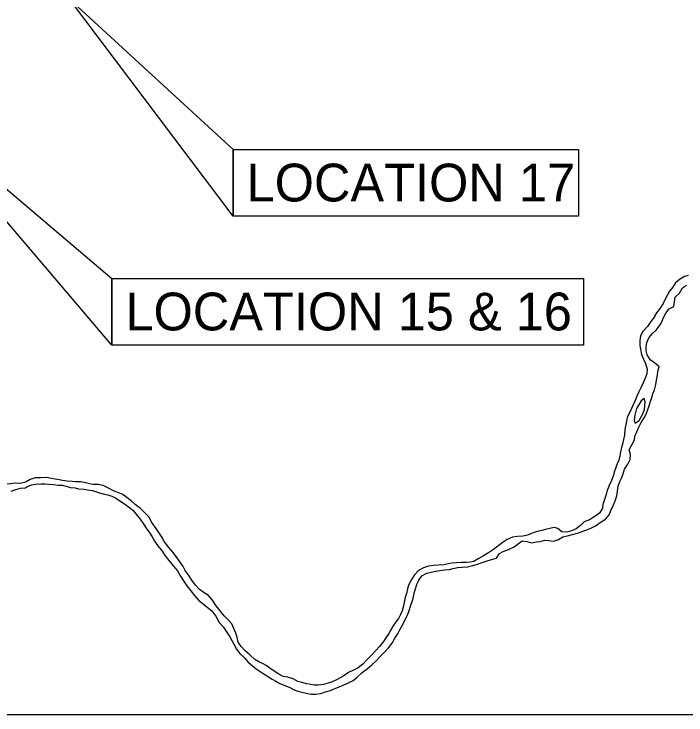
# Model space of a CAD drawing. Extents: x 0 to 34, y 0 to 22.
# Drawn here: x 10.628 to 13.652, y 13.067 to 16.221 of the extents above; entities that cross this region are included whole.
import ezdxf

# ---------------------------------------------------------------- set-up
doc = ezdxf.new("R2010")
doc.units = 0
for name, color, linetype in [('BR_P_Gen_Text', 7, 'Continuous'), ('GM_X_Major_River', 7, 'Continuous'), ('SH_Text', 7, 'Continuous')]:
    doc.layers.add(name, color=color, linetype=linetype)

msp = doc.modelspace()

# ---------------------------------------------------------------- linework, layer by layer
at = {"layer": 'BR_P_Gen_Text'}
for points in [[(11.6138, 15.6114), (11.6138, 15.3112), (10.8775, 16.2902)], [(11.0687, 15.0311), (11.0687, 14.7309), (10.1479, 15.8121)], [(11.6138, 15.6114), (13.1673, 15.6114), (13.1673, 15.3112), (11.6138, 15.3112)], [(11.0687, 15.0311), (13.1902, 15.0311), (13.1902, 14.7309), (11.0687, 14.7309)]]:
    msp.add_lwpolyline(points, close=True, dxfattribs=at)
at = {"layer": 'GM_X_Major_River'}
for points in [[(13.662, 15.0452), (13.6454, 15.0406), (13.6225, 15.0271), (13.604, 15.0116), (13.5907, 14.9911), (13.5773, 14.975), (13.5678, 14.9583), (13.5589, 14.9416), (13.5494, 14.9192), (13.5361, 14.8974), (13.5183, 14.8774), (13.5101, 14.8614), (13.5094, 14.8588)], [(13.5459, 14.8417), (13.5484, 14.8533), (13.5605, 14.8751), (13.5764, 14.895), (13.5968, 14.9053), (13.6005, 14.9258), (13.603, 14.9476), (13.6221, 14.9656), (13.636, 14.9887), (13.6539, 15.001)], [(13.5094, 14.8588), (13.4942, 14.8383), (13.4789, 14.8152), (13.4573, 14.7933), (13.4472, 14.7734), (13.4441, 14.7529), (13.4435, 14.7305), (13.4468, 14.7139), (13.452, 14.689), (13.4598, 14.6685), (13.4694, 14.6481), (13.4766, 14.6232), (13.476, 14.6021), (13.4678, 14.5822), (13.459, 14.561), (13.4482, 14.5392), (13.44, 14.5206), (13.4311, 14.502), (13.4235, 14.4828), (13.4134, 14.4623), (13.4064, 14.4462), (13.3975, 14.427), (13.3874, 14.4077), (13.3837, 14.3898), (13.3799, 14.3674), (13.3768, 14.3514), (13.3743, 14.3264), (13.3712, 14.3072), (13.3681, 14.2912), (13.3618, 14.2713), (13.3568, 14.2508), (13.3543, 14.2335), (13.3493, 14.2136), (13.3417, 14.197), (13.3366, 14.1803), (13.3303, 14.1636), (13.3234, 14.1419), (13.3158, 14.1226), (13.3063, 14.0995), (13.2975, 14.0771), (13.2905, 14.054), (13.2855, 14.0374), (13.2779, 14.0143), (13.2761, 13.9976), (13.2621, 13.9758), (13.2373, 13.9565), (13.2169, 13.9449), (13.1939, 13.9364), (13.1767, 13.9191), (13.1576, 13.9043), (13.1372, 13.8958), (13.1148, 13.89), (13.0931, 13.8905), (13.0751, 13.9058), (13.0585, 13.9102), (13.0387, 13.9056), (13.0195, 13.901), (13.0029, 13.8965), (12.9819, 13.8925), (12.9595, 13.8854), (12.9385, 13.8763), (12.918, 13.8717), (12.8938, 13.8697), (12.8708, 13.8677), (12.8465, 13.8573), (12.8242, 13.8418), (12.8045, 13.827), (12.7854, 13.8116), (12.7624, 13.7961), (12.7401, 13.7825), (12.7172, 13.7703), (12.6974, 13.758), (12.6808, 13.7541), (12.6635, 13.7527), (12.6412, 13.7526), (12.6188, 13.7512), (12.5984, 13.7505), (12.5817, 13.7478), (12.562, 13.7433), (12.5377, 13.7406), (12.5153, 13.7392), (12.4929, 13.7372), (12.4706, 13.7287), (12.4483, 13.7177), (12.4305, 13.6972), (12.4159, 13.676), (12.4032, 13.651), (12.3969, 13.6292), (12.3938, 13.6132)], [(12.6234, 13.7308), (12.6451, 13.7315), (12.6687, 13.7336), (12.6924, 13.7394), (12.7096, 13.744), (12.7307, 13.7511), (12.753, 13.7596), (12.7766, 13.7661), (12.799, 13.772), (12.8129, 13.7931), (12.8295, 13.8022), (12.8537, 13.8119), (12.878, 13.8235), (12.8984, 13.8384), (12.9149, 13.85), (12.936, 13.8481), (12.9572, 13.8412), (12.9789, 13.8458), (12.9961, 13.8484), (13.0166, 13.853), (13.0338, 13.8525), (13.0562, 13.8487), (13.0773, 13.8572), (13.0977, 13.8694), (13.1187, 13.8727), (13.1417, 13.8786), (13.1641, 13.8851), (13.1807, 13.8916), (13.2017, 13.8981), (13.224, 13.9084), (13.2438, 13.9188), (13.2693, 13.9355), (13.2891, 13.9478), (13.3062, 13.9684), (13.3157, 13.9902), (13.3259, 14.012), (13.3328, 14.0312), (13.341, 14.053), (13.3428, 14.0741), (13.3472, 14.0965), (13.3542, 14.117), (13.3611, 14.1331), (13.3694, 14.1523), (13.3757, 14.1728), (13.3896, 14.1953), (13.4004, 14.2171), (13.4016, 14.2389), (13.3964, 14.26), (13.4078, 14.2824), (13.4205, 14.3049), (13.421, 14.3215), (13.4305, 14.3414), (13.44, 14.3619), (13.4502, 14.3831), (13.4635, 14.4043), (13.473, 14.4203), (13.4799, 14.4415), (13.4856, 14.4575), (13.4913, 14.4793), (13.4982, 14.496), (13.502, 14.5126), (13.5102, 14.5299), (13.5165, 14.5543), (13.5196, 14.5741), (13.5234, 14.5965), (13.5246, 14.6138), (13.5309, 14.6343), (13.5078, 14.6528), (13.4917, 14.6636), (13.4769, 14.6878), (13.4724, 14.7064), (13.4723, 14.7224), (13.4761, 14.7435), (13.4843, 14.7646), (13.5008, 14.7839), (13.5174, 14.7987), (13.5352, 14.8225), (13.5459, 14.8417)], [(13.4631, 14.4913), (13.4497, 14.481), (13.4288, 14.4463), (13.4212, 14.4156), (13.4182, 14.3925), (13.4233, 14.3798)], [(13.4233, 14.3798), (13.4412, 14.3926), (13.4551, 14.4164), (13.4652, 14.4414), (13.4683, 14.4766), (13.4631, 14.4913)], [(12.3938, 13.6132), (12.3887, 13.5972), (12.3856, 13.5811), (12.38, 13.5587), (12.3743, 13.5357), (12.3667, 13.519), (12.3578, 13.5017), (12.3464, 13.4856), (12.3343, 13.4683), (12.3242, 13.4503), (12.3147, 13.4343), (12.3013, 13.4137), (12.2899, 13.397), (12.2727, 13.3752), (12.2568, 13.3566), (12.2365, 13.3366), (12.2174, 13.3173), (12.1977, 13.2961), (12.176, 13.2787), (12.1556, 13.2684), (12.1333, 13.258), (12.1122, 13.2439), (12.0957, 13.2335), (12.0784, 13.2258), (12.0599, 13.2167), (12.0421, 13.2102), (12.021, 13.2044), (11.9967, 13.2011), (11.9801, 13.201), (11.9622, 13.2035), (11.9462, 13.2079), (11.9225, 13.2129), (11.9046, 13.2179), (11.8835, 13.2299), (11.8598, 13.2375), (11.8393, 13.2406), (11.8195, 13.2507), (11.781, 13.2761), (11.765, 13.2876), (11.7464, 13.2984), (11.7304, 13.3066), (11.7124, 13.3174), (11.6893, 13.3378), (11.6675, 13.3562), (11.6495, 13.3753), (11.6373, 13.3944), (11.6321, 13.4175), (11.6269, 13.4353), (11.6179, 13.4558), (11.6076, 13.4775), (11.5902, 13.4972), (11.5742, 13.5138), (11.5555, 13.5355), (11.5382, 13.5578), (11.5214, 13.5839), (11.5028, 13.6049), (11.4797, 13.6195), (11.4631, 13.6323), (11.4451, 13.6514), (11.4284, 13.6737), (11.4142, 13.6947), (11.3988, 13.7171), (11.3885, 13.7349), (11.3756, 13.7553), (11.3582, 13.7796), (11.3428, 13.7993), (11.3248, 13.8203), (11.3055, 13.8465), (11.2952, 13.8656), (11.2804, 13.888), (11.2676, 13.9058), (11.2483, 13.9332), (11.2341, 13.9588), (11.2155, 13.9779), (11.1956, 13.997), (11.1731, 14.0141), (11.1545, 14.0307), (11.1302, 14.0498), (11.1141, 14.0612), (11.0981, 14.0662), (11.0764, 14.0757), (11.0527, 14.0884), (11.029, 14.0992), (11.0066, 14.1035), (10.9848, 14.1041), (10.9682, 14.1078), (10.9503, 14.1122), (10.9285, 14.116), (10.9055, 14.1158), (10.8895, 14.117), (10.8672, 14.1195), (10.8467, 14.1226), (10.8307, 14.1257), (10.8128, 14.1282), (10.7968, 14.1319), (10.7744, 14.135), (10.7469, 14.1349), (10.7239, 14.1335), (10.7003, 14.127), (10.6821, 14.1165), (10.6751, 14.1134)], [(10.6751, 14.1134), (10.6541, 14.1081), (10.633, 14.1099), (10.6113, 14.1078), (10.5889, 14.105)], [(10.6804, 14.0897), (10.6855, 14.0937), (10.7074, 14.1033), (10.7247, 14.1053), (10.749, 14.1067), (10.7662, 14.1075), (10.7841, 14.1056), (10.8065, 14.1038), (10.8276, 14.1014), (10.8442, 14.1008), (10.8666, 14.0958), (10.8826, 14.0908), (10.9035, 14.0887), (10.9184, 14.0852)], [(10.6147, 14.0745), (10.6364, 14.0817), (10.658, 14.087), (10.6804, 14.0897)], [(10.9184, 14.0852), (10.9427, 14.0834), (10.9587, 14.0809), (10.9805, 14.0772), (11.0125, 14.0671), (11.0285, 14.0627), (11.0509, 14.0577), (11.0675, 14.052), (11.0842, 14.0438), (11.1047, 14.0304), (11.1252, 14.0177), (11.1412, 14.0057), (11.1643, 13.9872), (11.1829, 13.9649), (11.1952, 13.9483), (11.2119, 13.9247), (11.2228, 13.9082), (11.2389, 13.8858), (11.2492, 13.868), (11.2608, 13.8488), (11.2749, 13.8278), (11.2942, 13.8048), (11.3084, 13.7832), (11.3251, 13.7615), (11.3463, 13.7366), (11.363, 13.7156), (11.3739, 13.6964), (11.39, 13.6709), (11.4055, 13.648), (11.4235, 13.6257), (11.4402, 13.6053), (11.4601, 13.5823), (11.4793, 13.5677), (11.4967, 13.5524), (11.5178, 13.5353), (11.5358, 13.5123), (11.5513, 13.4836), (11.5693, 13.4632), (11.5866, 13.4371), (11.5989, 13.4192), (11.6079, 13.402), (11.6169, 13.3854), (11.6291, 13.3631), (11.6446, 13.3433), (11.6645, 13.3236), (11.6805, 13.3057), (11.703, 13.286), (11.7222, 13.272), (11.744, 13.2568), (11.7652, 13.2434), (11.7895, 13.2282), (11.8055, 13.2187), (11.8248, 13.2092), (11.8433, 13.2016), (11.8689, 13.1902), (11.8888, 13.1801), (11.9054, 13.1744), (11.9227, 13.1694), (11.9426, 13.165), (11.9649, 13.1612), (11.9867, 13.1607), (12.0084, 13.1634), (12.0301, 13.1705), (12.0524, 13.177), (12.0754, 13.188), (12.0952, 13.1945), (12.1118, 13.2029), (12.1354, 13.2133), (12.1539, 13.2223), (12.1723, 13.2365), (12.1946, 13.2577), (12.2182, 13.2757), (12.2373, 13.2912), (12.2577, 13.3105), (12.2768, 13.3311), (12.2971, 13.351), (12.3137, 13.3696), (12.3295, 13.3908), (12.3422, 13.412), (12.3568, 13.4351), (12.3663, 13.4537), (12.3778, 13.4736), (12.3873, 13.4941), (12.3974, 13.5127), (12.4037, 13.5288), (12.4157, 13.5653), (12.4208, 13.5826), (12.4252, 13.5986), (12.4289, 13.6146), (12.4333, 13.6307), (12.4409, 13.6544), (12.4498, 13.673), (12.4637, 13.6929), (12.4854, 13.7045), (12.5058, 13.7104), (12.5263, 13.7143), (12.5435, 13.7169), (12.5652, 13.7202), (12.587, 13.7223), (12.6042, 13.7262), (12.6234, 13.7308)]]:
    msp.add_lwpolyline(points, dxfattribs=at)
at = {"layer": 'SH_Text'}
msp.add_lwpolyline([(1.9289, 20.907), (19.068, 20.907), (19.068, 13.067), (1.9289, 13.067)], close=True, dxfattribs=at)

# ---------------------------------------------------------------- texts
at = {"layer": 'BR_P_Gen_Text'}
for s, p in [('LOCATION 17', (11.6745, 15.378)), ('LOCATION 15 & 16', (11.1294, 14.7977))]:
    msp.add_text(s, height=0.17, dxfattribs=at).set_placement(p)

doc.saveas('drawing.dxf')
